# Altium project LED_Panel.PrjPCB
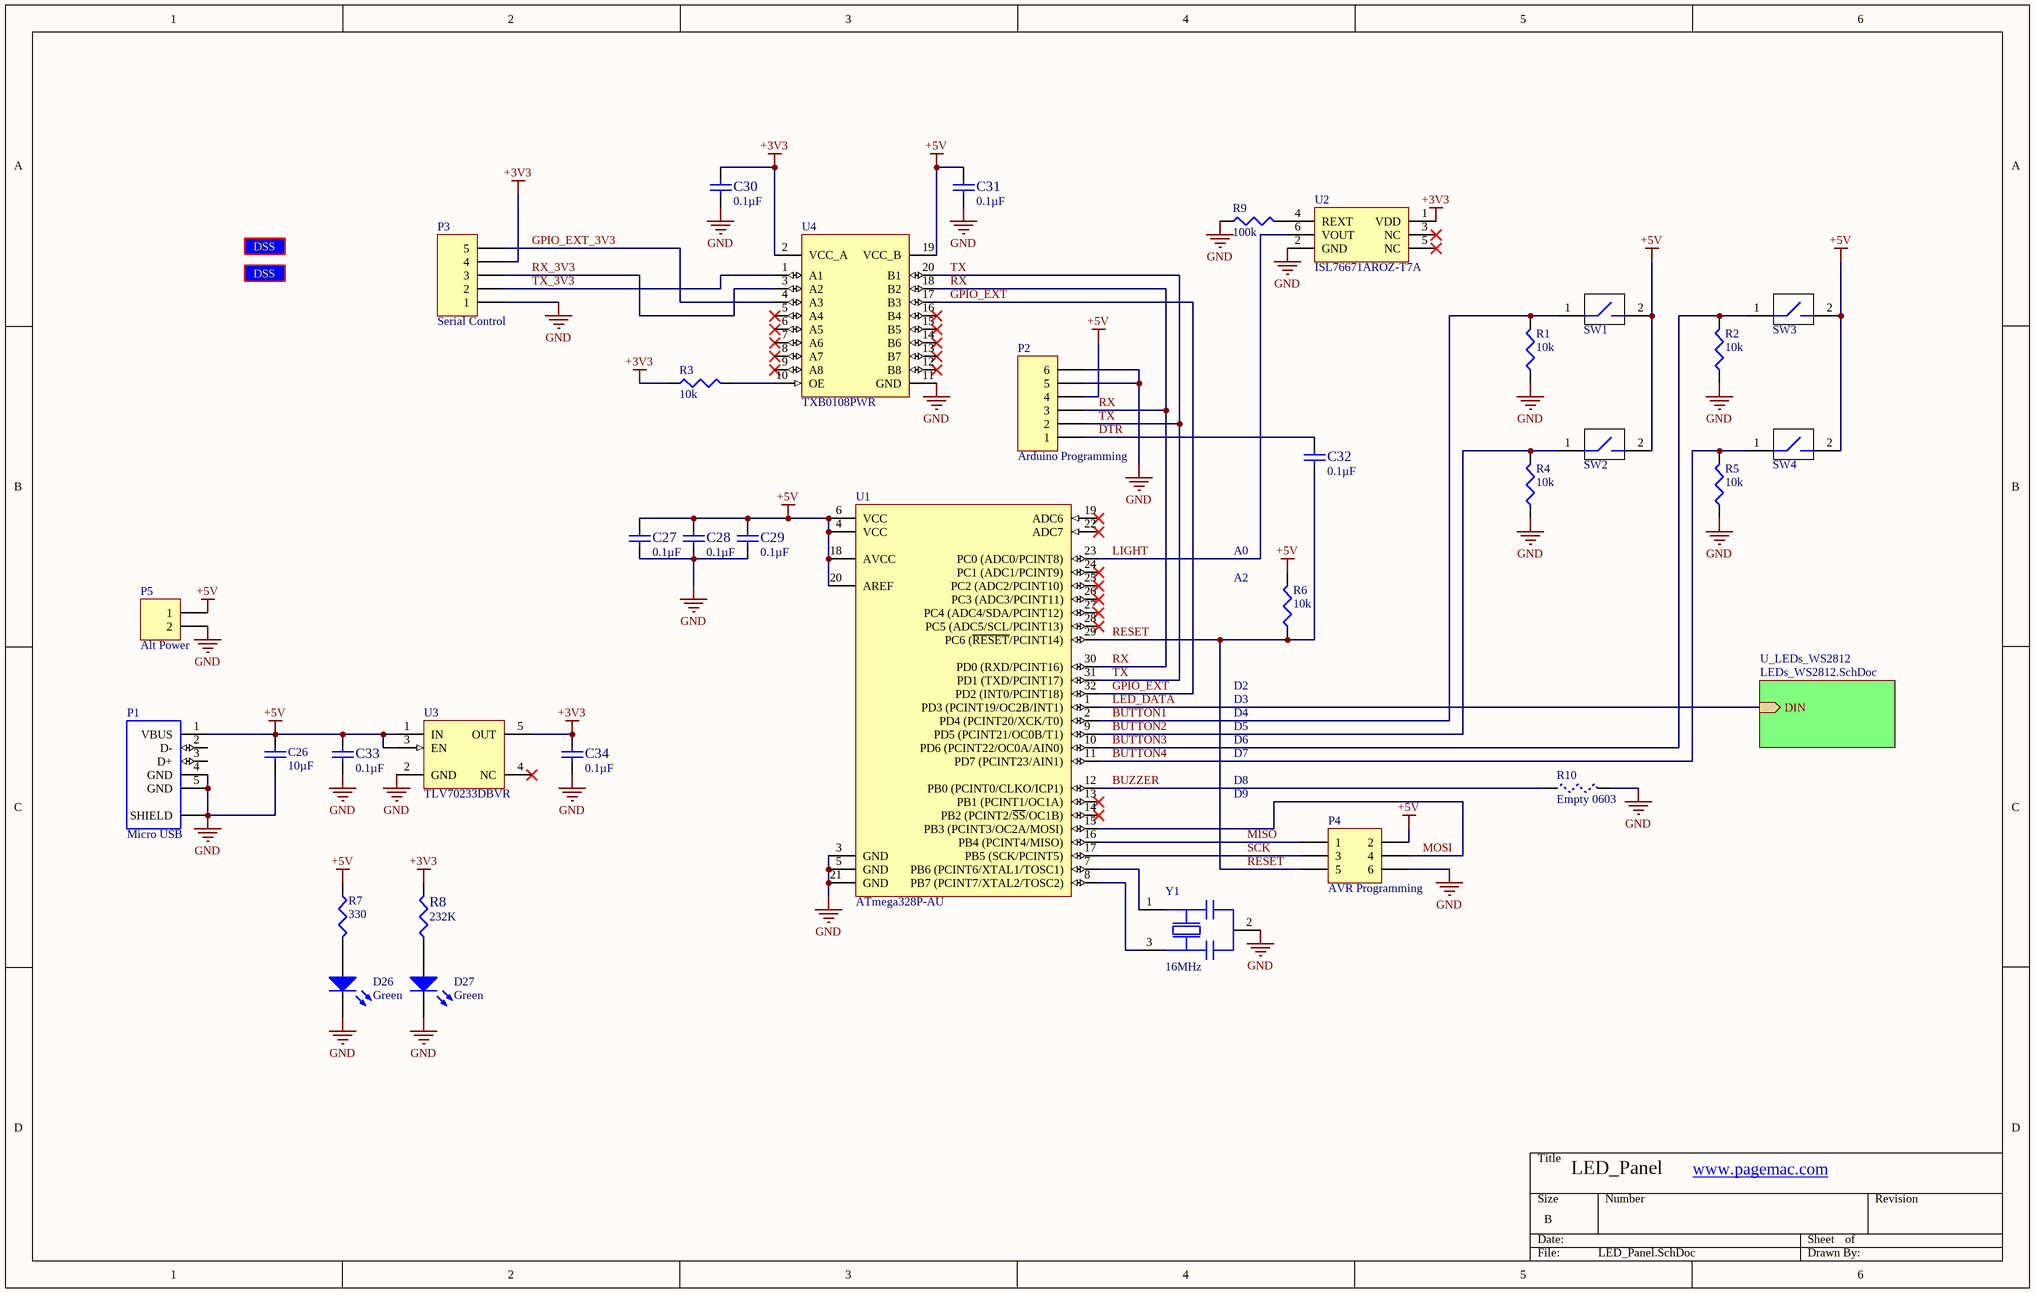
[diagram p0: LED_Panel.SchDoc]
2 sheets, 87 parts. Net scope: hierarchical (ports join the sheet entries above them; power ports are global).
Board file: LED_Panel.PcbDoc
Sheets:
  LED_Panel.SchDoc
    U_LEDs_WS2812 = LEDs_WS2812.SchDoc

## Sheet LED_Panel.SchDoc
size B; PageSetup: Record=PageOptions¦CenterHorizontal=True¦CenterVertical=True¦PrintScale=1.12¦XCorrection=1.00¦YCorrection=1.00¦PrintKind=0¦BorderSize=5000000¦LeftOffset=0¦BottomOffset=0¦Orientation=2¦PaperLength=1000¦PaperWidth=1000¦Scale=100¦PaperSource=7¦PrintQuality=-3¦MediaType=1¦DitherType=10¦PrintScaleMode=1¦PaperKind=11 x 17¦PaperIndex=119

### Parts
C26  Capacitance: 10µF  [C0603]  (hidden comment: C1608X5R1A106M080AC)
C27  Capacitance: 0.1µF  [C0603]  (hidden comment: CC0603KRX7R9BB104)
C28  Capacitance: 0.1µF  [C0603]  (hidden comment: CC0603KRX7R9BB104)
C29  Capacitance: 0.1µF  [C0603]  (hidden comment: CC0603KRX7R9BB104)
C30  Capacitance: 0.1µF  [C0603]  (hidden comment: CC0603KRX7R9BB104)
C31  Capacitance: 0.1µF  [C0603]  (hidden comment: CC0603KRX7R9BB104)
C32  Capacitance: 0.1µF  [C0603]  (hidden comment: CC0603KRX7R9BB104)
C33  Capacitance: 0.1µF  [C0603]  (hidden comment: CC0603KRX7R9BB104)
C34  Capacitance: 0.1µF  [C0603]  (hidden comment: CC0603KRX7R9BB104)
D26  Color: Green  [LED_0603]  (hidden comment: LTST-C190KGKT)
D27  Color: Green  [LED_0603]  (hidden comment: LTST-C190KGKT)
P1  Micro USB  [FCI/10118192-0001LF]
P2  Arduino Programming  [HDR1X6]
P3  Serial Control  [HDR1X5]
P4  AVR Programming  [HDR2X3]
P5  Alt Power  [HDR1X2]
R1  Resistance (Ohms): 10k  [R0603]  (hidden comment: ERJ-3EKF1002V)
R2  Resistance (Ohms): 10k  [R0603]  (hidden comment: ERJ-3EKF1002V)
R3  Resistance (Ohms): 10k  [R0603]  (hidden comment: ERJ-3EKF1002V)
R4  Resistance (Ohms): 10k  [R0603]  (hidden comment: ERJ-3EKF1002V)
R5  Resistance (Ohms): 10k  [R0603]  (hidden comment: ERJ-3EKF1002V)
R6  Resistance (Ohms): 10k  [R0603]  (hidden comment: ERJ-3EKF1002V)
R7  Resistance (Ohms): 330  [R0603]  (hidden comment: ERJ-3GEYJ331V)
R8  Resistance (Ohms): 232K  [R0603]  (hidden comment: RC0603FR-07232KL)
R9  Resistance (Ohms): 100k  [R0603]  (hidden comment: ERJ-3EKF1003V)
R10  Empty 0603  [R0603_BLANK]  (no BOM)
SS1  DSS  [DSS_LOGO]  (value not drawn)
SS2  DSS  [DSS_LOGO]  (value not drawn)
SW1  FSMRA6JH  [SWITCH_RA]  (value not drawn)
SW2  FSMRA6JH  [SWITCH_RA]  (value not drawn)
SW3  FSMRA6JH  [SWITCH_RA]  (value not drawn)
SW4  FSMRA6JH  [SWITCH_RA]  (value not drawn)
U1  ATmega328P-AU  [TQFP-32]
U2  ISL76671AROZ-T7A  [ODFN-6]
U3  TLV70233DBVR  [SOT23-5]
U4  TXB0108PWR  [TSSOP-20]
Y1  Frequency: 16MHz  [MURATA_CRYSTAL]  (hidden comment: CSTCE16M0V53-R0)

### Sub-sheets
U_LEDs_WS2812 = LEDs_WS2812.SchDoc: DIN (in)

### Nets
+3V3: C30.1 C34.1 P3.4 R3.1 R8.2 U2.1(VDD) U3.5(OUT) U4.2(VCC_A)
+5V: C26.1 C27.1 C28.1 C29.1 C31.1 C33.1 P1.1(VBUS) P2.4 P4.2 P5.1 R6.2 R7.1 SW1.2 SW2.2 SW3.2 SW4.2 U1.4(VCC) U1.6(VCC) U1.18(AVCC) U1.20(AREF) U3.1(IN) U3.3(EN) U4.19(VCC_B)
GND: C26.2 C27.2 C28.2 C29.2 C30.2 C31.2 C33.2 C34.2 D26.2 D27.2 P1.4(GND) P1.5(GND) P1.6(SHIELD) P2.5 P2.6 P3.1 P4.6 P5.2 R1.1 R2.1 R4.1 R5.1 R9.1 R10.2 U1.3(GND) U1.5(GND) U1.21(GND) U2.2(GND) U3.2(GND) U4.11(GND) Y1.2
BUTTON1: R1.2 SW1.1 U1.2(PD4_(PCINT20/XCK/T0))
BUTTON2: R4.2 SW2.1 U1.9(PD5_(PCINT21/OC0B/T1))
BUTTON3: R2.2 SW3.1 U1.10(PD6_(PCINT22/OC0A/AIN0))
BUTTON4: R5.2 SW4.1 U1.11(PD7_(PCINT23/AIN1))
BUZZER: R10.1 U1.12(PB0_(PCINT0/CLKO/ICP1))
DTR: C32.1 P2.1
GPIO_EXT: U1.32(PD2_(INT0/PCINT18)) U4.17(B3)
GPIO_EXT_3V3: P3.5 U4.4(A3)
LED_DATA: U1.1(PD3_(PCINT19/OC2B/INT1)) ; sheet U_LEDs_WS2812/DIN  [project net DIN]
LIGHT: U1.23(PC0_(ADC0/PCINT8)) U2.6(VOUT)
MISO: P4.1 U1.16(PB4_(PCINT4/MISO))
MOSI: P4.4 U1.15(PB3_(PCINT3/OC2A/MOSI))
RESET: C32.2 P4.5 R6.1 U1.29(PC6_(~{RESET}/PCINT14))
RX: P2.3 U1.30(PD0_(RXD/PCINT16)) U4.18(B2)
RX_3V3: P3.3 U4.3(A2)
SCK: P4.3 U1.17(PB5_(SCK/PCINT5))
TX: P2.2 U1.31(PD1_(TXD/PCINT17)) U4.20(B1)
TX_3V3: P3.2 U4.1(A1)
NetD26_1: D26.1 R7.2
NetD27_1: D27.1 R8.1
NetR3_2: R3.2 U4.10(OE)
NetR9_2: R9.2 U2.4(REXT)
NetU1_7: U1.7(PB6_(PCINT6/XTAL1/TOSC1)) Y1.1
NetU1_8: U1.8(PB7_(PCINT7/XTAL2/TOSC2)) Y1.3

Not connected (* = marked no-connect by the designer): P1 2(D-) 3(D+); U1 13(PB1_(PCINT1/OC1A))* 14(PB2_(PCINT2/~{SS}/OC1B))* 19(ADC6)* 22(ADC7)* 24(PC1_(ADC1/PCINT9))* 25(PC2_(ADC2/PCINT10))* 26(PC3_(ADC3/PCINT11))* 27(PC4_(ADC4/SDA/PCINT12))* 28(PC5_(ADC5/SCL/PCINT13))*; U2 3(NC)* 5(NC)*; U3 4(NC)*; U4 5(A4)* 6(A5)* 7(A6)* 8(A7)* 9(A8)* 12(B8)* 13(B7)* 14(B6)* 15(B5)* 16(B4)*

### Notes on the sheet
- (near R6) A0
- (near R6) A2
- D2
- D3
- D4
- D5
- D6
- D7
- D8
- D9
- LED_Panel
- www.pagemac.com

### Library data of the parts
C26 = C1608X5R1A106M080AC: CAP CER 10UF 10V 20% X5R 0603; Manufacturer: TDK Corporation
C27-C34 = CC0603KRX7R9BB104: CAP CER 0.1UF 50V 10% X7R 0603; Manufacturer: Yageo
D26 D27 = LTST-C190KGKT: LED GREEN CLEAR 0603 SMD; Manufacturer: Lite-On Inc; Wavelength - Dominant: 571nm; Wavelength - Peak: 574nm; Millicandela Rating: 35mcd; Voltage - Forward (Vf) Typ: 2V; Current - Test: 20mA; Viewing Angle: 130°; Lens Style/Size: Rectangle with Flat Top, 1.06mm x 0.8mm
P1 = 10118192-0001LF: CONN USB MICRO B RECPT SMT R/A; Manufacturer: FCI; Connector Type: USB - micro B; Number of Contacts: 5; Gender: Receptacle; Specifications: USB 2.0
P2 = Header 6: Header, 6-Pin
P3 = Header 5: Header, 5-Pin
P4 = Header 3X2: Header, 3-Pin, Dual row
P5 = Header 2: Header, 2-Pin
R1-R6 = ERJ-3EKF1002V: RES 10.0K OHM 1/10W 1% 0603 SMD; Manufacturer: Panasonic Electronic Components; Power (Watts): 0.1W, 1/10W; Temperature Coefficient: ±100ppm/°C
R7 = ERJ-3GEYJ331V: RES 330 OHM 1/10W 5% 0603 SMD; Manufacturer: Panasonic Electronic Components; Power (Watts): 0.1W, 1/10W; Temperature Coefficient: ±200ppm/°C
R8 = RC0603FR-07232KL: RES 232K OHM 1/10W 1% 0603 SMD; Manufacturer: Yageo; Power (Watts): 0.1W, 1/10W; Temperature Coefficient: ±100ppm/°C
R9 = ERJ-3EKF1003V: RES 100K OHM 1/10W 1% 0603 SMD; Manufacturer: Panasonic Electronic Components; Power (Watts): 0.1W, 1/10W; Temperature Coefficient: ±100ppm/°C
R10 = Blank-Res-0603: Empty 0603 Pads w/ Blank Resistor Puppet; Validated: Yes
SW1-SW4 = FSMRA6JH: SWITCH TACTILE SPST-NO 0.05A 12V; Manufacturer: TE Connectivity; Switch Function: Off-Mom; Contact Rating @ Voltage: 0.05A @ 24VDC; Actuator Type: Standard; Actuator Height off PCB, from Pins: 6.85mm; Actuator Orientation: Side Actuated; Outline: 7.10mm x 7.00mm; Illumination: Non-Illuminated; Operating Force: 160gf; Actuator Material: Polyamide (PA), Nylon; Switch Travel: 0.25mm; Mechanical Life: 100,000 Cycles
U1 = ATmega328P-AU: 8-bit AVR Microcontroller, 32KB Flash, 1KB EEPROM, 2KB SRAM, 32-pin TQFP, Industrial Grade (-40°C to 85°C)
U2 = ISL76671AROZ-T7A: IC AMBIENT LIGHT SENSOR; Manufacturer: Intersil; With Proximity Sensor: No; Wavelength: 550nm; Voltage - Supply: 1.8 V ~ 3 V; Output Type: Current
U3 = TLV70233DBVR: Single Output LDO, 300 mA, Fixed 3.3 V Output, 2 to 5.5 V Input, with Low IQ, 5-pin SOT-23 (DBV), -40 to 125 degC, Green (RoHS & no Sb/Br); Manufacturer: Texas Instruments; Accuracy(%): 2; Fixed Output Options(V): 3.3; Iout(Max)(A): 0.3; Iq(Typ)(mA): 0.03; SubFamily: Single Channel LDO; Vdo(Typ)(mV): 220; Vin(Max)(V): 5.5
U4 = TXB0108PWR: IC VOLT-LVL TRANSL 8BIT 20-TSSOP; Manufacturer: Texas Instruments; Logic Function: Translator, Bidirectional; Number of Bits: 8; Input Type: Logic; Data Rate: 100Mbps; Number of Outputs/Channel: 1; Differential - Input:Output: No/No; Propagation Delay (Max): 4ns; Voltage - Supply: 1.2 V ~ 3.6 V, 1.65 V ~ 5.5 V
Y1 = CSTCE16M0V53-R0: CER RESONATOR 16.0MHZ SMD; Manufacturer: Murata Electronics North America; Frequency Stability: ±0.3%; Frequency Tolerance: ±0.5%; Capacitance: 15pF

## Sheet LEDs_WS2812.SchDoc
size B
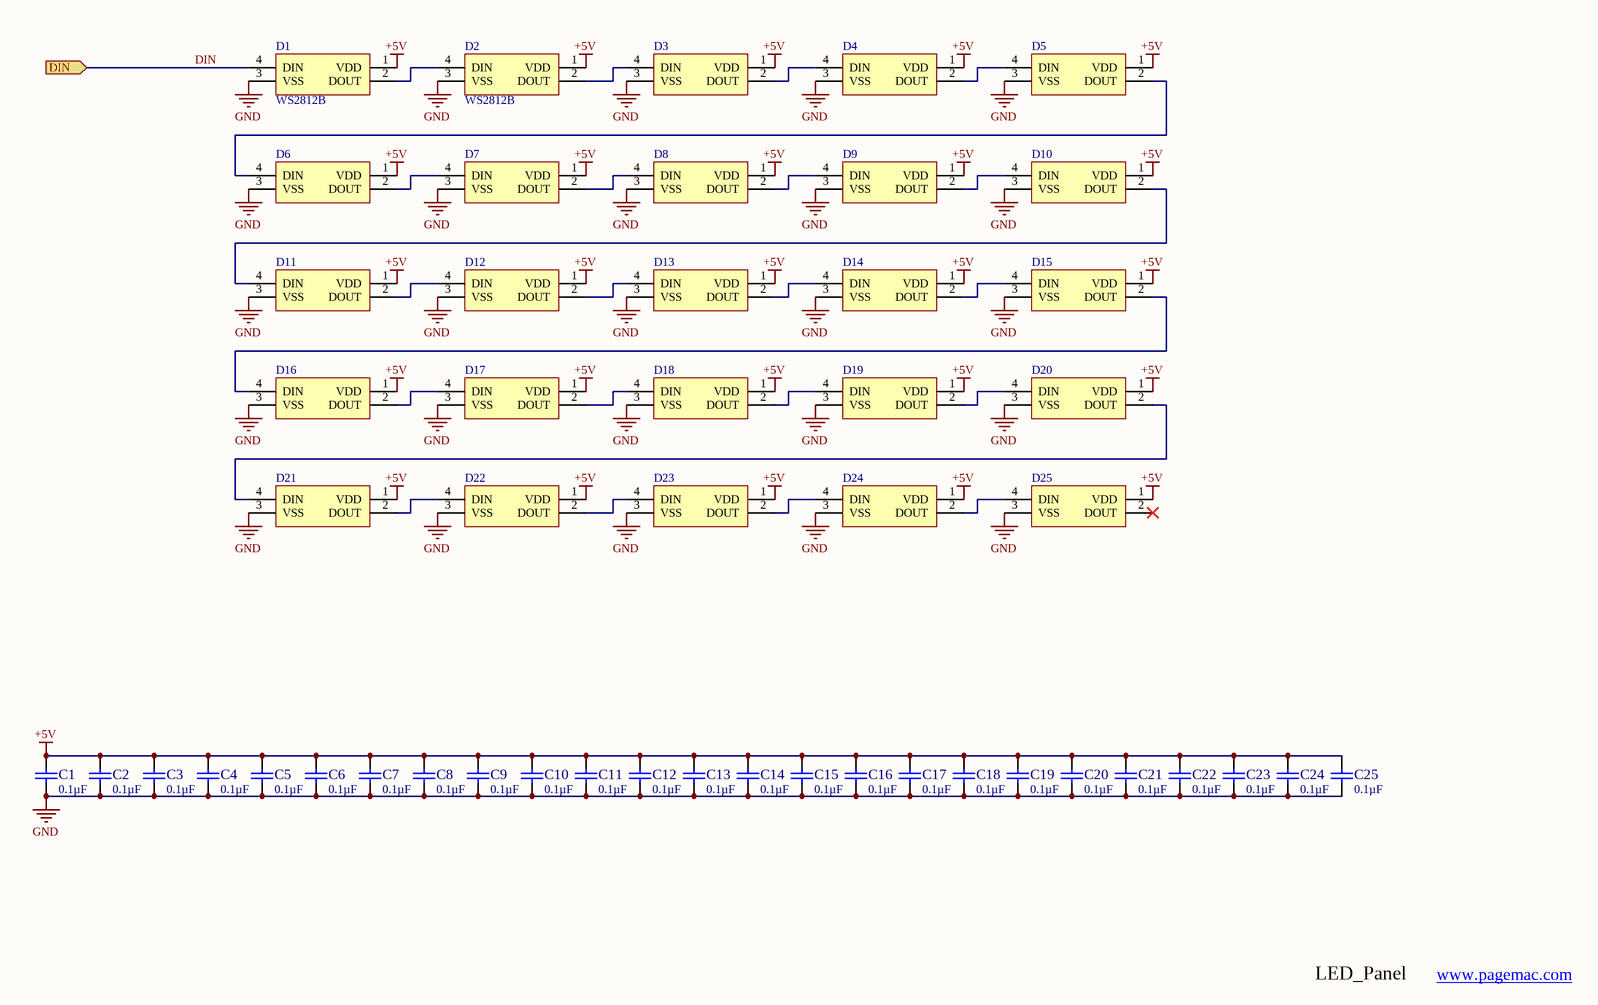
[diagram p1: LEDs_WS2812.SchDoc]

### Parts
C1  Capacitance: 0.1µF  [C0603]  (hidden comment: CC0603KRX7R9BB104)
C2  Capacitance: 0.1µF  [C0603]  (hidden comment: CC0603KRX7R9BB104)
C3  Capacitance: 0.1µF  [C0603]  (hidden comment: CC0603KRX7R9BB104)
C4  Capacitance: 0.1µF  [C0603]  (hidden comment: CC0603KRX7R9BB104)
C5  Capacitance: 0.1µF  [C0603]  (hidden comment: CC0603KRX7R9BB104)
C6  Capacitance: 0.1µF  [C0603]  (hidden comment: CC0603KRX7R9BB104)
C7  Capacitance: 0.1µF  [C0603]  (hidden comment: CC0603KRX7R9BB104)
C8  Capacitance: 0.1µF  [C0603]  (hidden comment: CC0603KRX7R9BB104)
C9  Capacitance: 0.1µF  [C0603]  (hidden comment: CC0603KRX7R9BB104)
C10  Capacitance: 0.1µF  [C0603]  (hidden comment: CC0603KRX7R9BB104)
C11  Capacitance: 0.1µF  [C0603]  (hidden comment: CC0603KRX7R9BB104)
C12  Capacitance: 0.1µF  [C0603]  (hidden comment: CC0603KRX7R9BB104)
C13  Capacitance: 0.1µF  [C0603]  (hidden comment: CC0603KRX7R9BB104)
C14  Capacitance: 0.1µF  [C0603]  (hidden comment: CC0603KRX7R9BB104)
C15  Capacitance: 0.1µF  [C0603]  (hidden comment: CC0603KRX7R9BB104)
C16  Capacitance: 0.1µF  [C0603]  (hidden comment: CC0603KRX7R9BB104)
C17  Capacitance: 0.1µF  [C0603]  (hidden comment: CC0603KRX7R9BB104)
C18  Capacitance: 0.1µF  [C0603]  (hidden comment: CC0603KRX7R9BB104)
C19  Capacitance: 0.1µF  [C0603]  (hidden comment: CC0603KRX7R9BB104)
C20  Capacitance: 0.1µF  [C0603]  (hidden comment: CC0603KRX7R9BB104)
C21  Capacitance: 0.1µF  [C0603]  (hidden comment: CC0603KRX7R9BB104)
C22  Capacitance: 0.1µF  [C0603]  (hidden comment: CC0603KRX7R9BB104)
C23  Capacitance: 0.1µF  [C0603]  (hidden comment: CC0603KRX7R9BB104)
C24  Capacitance: 0.1µF  [C0603]  (hidden comment: CC0603KRX7R9BB104)
C25  Capacitance: 0.1µF  [C0603]  (hidden comment: CC0603KRX7R9BB104)
D1  WS2812B  [WS2812B]
D2  WS2812B  [WS2812B]
D3  WS2812B  [WS2812B]  (value not drawn)
D4  WS2812B  [WS2812B]  (value not drawn)
D5  WS2812B  [WS2812B]  (value not drawn)
D6  WS2812B  [WS2812B]  (value not drawn)
D7  WS2812B  [WS2812B]  (value not drawn)
D8  WS2812B  [WS2812B]  (value not drawn)
D9  WS2812B  [WS2812B]  (value not drawn)
D10  WS2812B  [WS2812B]  (value not drawn)
D11  WS2812B  [WS2812B]  (value not drawn)
D12  WS2812B  [WS2812B]  (value not drawn)
D13  WS2812B  [WS2812B]  (value not drawn)
D14  WS2812B  [WS2812B]  (value not drawn)
D15  WS2812B  [WS2812B]  (value not drawn)
D16  WS2812B  [WS2812B]  (value not drawn)
D17  WS2812B  [WS2812B]  (value not drawn)
D18  WS2812B  [WS2812B]  (value not drawn)
D19  WS2812B  [WS2812B]  (value not drawn)
D20  WS2812B  [WS2812B]  (value not drawn)
D21  WS2812B  [WS2812B]  (value not drawn)
D22  WS2812B  [WS2812B]  (value not drawn)
D23  WS2812B  [WS2812B]  (value not drawn)
D24  WS2812B  [WS2812B]  (value not drawn)
D25  WS2812B  [WS2812B]  (value not drawn)

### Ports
DIN (in)

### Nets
+5V: C1.1 C2.1 C3.1 C4.1 C5.1 C6.1 C7.1 C8.1 C9.1 C10.1 C11.1 C12.1 C13.1 C14.1 C15.1 C16.1 C17.1 C18.1 C19.1 C20.1 C21.1 C22.1 C23.1 C24.1 C25.1 D1.1(VDD) D2.1(VDD) D3.1(VDD) D4.1(VDD) D5.1(VDD) D6.1(VDD) D7.1(VDD) D8.1(VDD) D9.1(VDD) D10.1(VDD) D11.1(VDD) D12.1(VDD) D13.1(VDD) D14.1(VDD) D15.1(VDD) D16.1(VDD) D17.1(VDD) D18.1(VDD) D19.1(VDD) D20.1(VDD) D21.1(VDD) D22.1(VDD) D23.1(VDD) D24.1(VDD) D25.1(VDD)
GND: C1.2 C2.2 C3.2 C4.2 C5.2 C6.2 C7.2 C8.2 C9.2 C10.2 C11.2 C12.2 C13.2 C14.2 C15.2 C16.2 C17.2 C18.2 C19.2 C20.2 C21.2 C22.2 C23.2 C24.2 C25.2 D1.3(VSS) D2.3(VSS) D3.3(VSS) D4.3(VSS) D5.3(VSS) D6.3(VSS) D7.3(VSS) D8.3(VSS) D9.3(VSS) D10.3(VSS) D11.3(VSS) D12.3(VSS) D13.3(VSS) D14.3(VSS) D15.3(VSS) D16.3(VSS) D17.3(VSS) D18.3(VSS) D19.3(VSS) D20.3(VSS) D21.3(VSS) D22.3(VSS) D23.3(VSS) D24.3(VSS) D25.3(VSS)
DIN: D1.4(DIN) ; port DIN
NetD1_2: D1.2(DOUT) D2.4(DIN)
NetD2_2: D2.2(DOUT) D3.4(DIN)
NetD3_2: D3.2(DOUT) D4.4(DIN)
NetD4_2: D4.2(DOUT) D5.4(DIN)
NetD5_2: D5.2(DOUT) D6.4(DIN)
NetD6_2: D6.2(DOUT) D7.4(DIN)
NetD7_2: D7.2(DOUT) D8.4(DIN)
NetD8_2: D8.2(DOUT) D9.4(DIN)
NetD9_2: D9.2(DOUT) D10.4(DIN)
NetD10_2: D10.2(DOUT) D11.4(DIN)
NetD11_2: D11.2(DOUT) D12.4(DIN)
NetD12_2: D12.2(DOUT) D13.4(DIN)
NetD13_2: D13.2(DOUT) D14.4(DIN)
NetD14_2: D14.2(DOUT) D15.4(DIN)
NetD15_2: D15.2(DOUT) D16.4(DIN)
NetD16_2: D16.2(DOUT) D17.4(DIN)
NetD17_2: D17.2(DOUT) D18.4(DIN)
NetD18_2: D18.2(DOUT) D19.4(DIN)
NetD19_2: D19.2(DOUT) D20.4(DIN)
NetD20_2: D20.2(DOUT) D21.4(DIN)
NetD21_2: D21.2(DOUT) D22.4(DIN)
NetD22_2: D22.2(DOUT) D23.4(DIN)
NetD23_2: D23.2(DOUT) D24.4(DIN)
NetD24_2: D24.2(DOUT) D25.4(DIN)

Not connected (* = marked no-connect by the designer): D25 2(DOUT)*

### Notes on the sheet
- LED_Panel
- www.pagemac.com

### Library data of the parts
C1-C25 = CC0603KRX7R9BB104: as C27 on sheet LED_Panel
D1-D25 = WS2812B: RGB LED WITH CONTROLLER

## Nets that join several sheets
+5V: LED_Panel (23 pins), LEDs_WS2812 (50 pins)
GND: LED_Panel (31 pins), LEDs_WS2812 (50 pins)
DIN: LED_Panel (U1.1), LEDs_WS2812 (D1.4)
